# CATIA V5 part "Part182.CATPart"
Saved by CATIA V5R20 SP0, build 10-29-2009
Part number: FA 126700-2 comprimido
Revision: ANY
Definition: UNKNOWN
Nomenclature: FA 126700-2 comprimido
Source: Unknown
Bounding box of the stored display mesh (mm): x -2.8 to 2.8, y 0 to 5, z -2.8 to 2.8
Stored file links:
  C:\Users\Utente\Desktop\IO LAVORO\3D X SITO CF\CUMSA\3D files FA\FA 126712-20\Part182.CATPart

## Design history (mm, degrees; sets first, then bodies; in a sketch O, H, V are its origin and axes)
Body1 "Cortar-Extruir1" (main body)
  Solid1: solid without history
